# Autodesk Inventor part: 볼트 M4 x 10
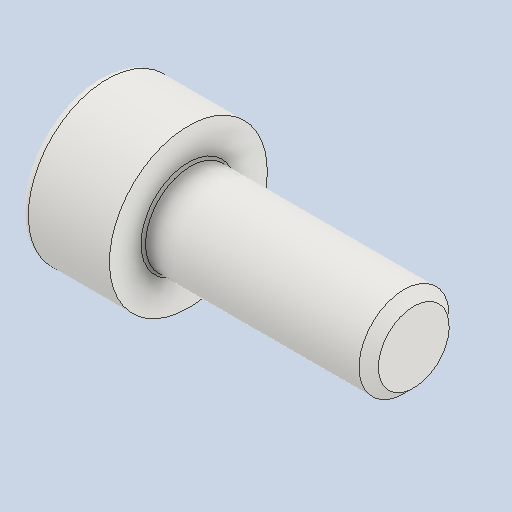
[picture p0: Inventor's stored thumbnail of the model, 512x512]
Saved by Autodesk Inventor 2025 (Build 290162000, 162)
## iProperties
Created: 2024-07
Part Number: 볼트 M4 x 10
Material: 강철, 연강
Description: 6각머리 태핑 나사
Document SubType Name: Modeling
Designer: 학생
Density: 7.86 g/cm^3
Appearance: 기본값
Author: jhkim
Revision Number: 1
Sending System: Autodesk Inventor 2025
Preprocessor: ST-DEVELOPER v20
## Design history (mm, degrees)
feature "Solid1"
node "솔리드1"
